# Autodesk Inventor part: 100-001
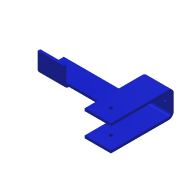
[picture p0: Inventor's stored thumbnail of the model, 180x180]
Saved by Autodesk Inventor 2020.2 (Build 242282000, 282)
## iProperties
Created: 2014-01
Part Number: 100-001
Material: Ogólny
Document SubType Name: Modeling
Designer: F.Stasiak
Density: 1 g/cm^3
Appearance: Niebieska - farba ścienna - lśniąca
Manager: www.cadconsulting.pl
Company: Fabian Stasiak CAD Consulting
Author: F.Stasiak
Subject: Zbiór ćwiczeń. Autodesk Inventor 2020. Kurs podstawowy
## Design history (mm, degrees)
sketch "Szkic2"
  geometry: L1 (20, 120)-(20, 5); L2 (20, 5)-(-20, 5); L3 (-20, 5)-(-20, 120); L4 (-25, 120)-(-25, 0); L5 (-25, 0)-(25, 0); L6 (25, 0)-(25, 120); L7 (25, 120)-(20, 120); L8 (-20, 120)-(-25, 120); 2 further points
  constraints: 16 end point, 3 equal length, 3 perpendicular, 1 coincident, 1 midpoint, 1 parallel, 1 vertical, 2 other
  dimensions: "d2" = 5 distance of L6.end L1.start; "d3" = 120 distance of L5.end L6.end; "d4" = 50 distance between parallel lines of L6 L4
extrude "Wyciągnięcie proste1" new body sketch "Szkic2" stored distance "d5" = 50; taper "d6" = 0 deg
fillet "Zaokrąglenie1" dims "d7" = 5
fillet "Zaokrąglenie2" dims "d8" = 10
sketch "Szkic3"
  geometry: L1 (50, 0)-(50, -30) reference; L2 (12.5, -15)-(37.5, -15); 4 further points
  constraints: 3 coincident, 2 end point, 1 midpoint, 1 perpendicular
  dimensions: "d9" = 25 distance of L2.start L2.end
hole "Otwór1" sketch "Szkic3" at (12.5, -15), (37.5, -15) diameter "d10" = 6.5; stored, may be unused: countersink angle "d14" = 90 deg, drill point angle "d16" = 118 deg; dims "d11" = 6, "d12" = 4, "d13" = 2, "d15" = 8
sketch "Szkic4"
  geometry: L1 (0, 0)-(50, 0) reference; 3 further points
  constraints: 1 midpoint, 1 vertical alignment
  dimensions: "d17" = 25 distance from line of L1 point (25, 25)
hole "Otwór2" sketch "Szkic4" at (25, 25) diameter "d18" = 6.5; stored, may be unused: countersink angle "d22" = 90 deg, drill point angle "d24" = 118 deg; dims "d19" = 6, "d20" = 4, "d21" = 2, "d23" = 8
sketch "Szkic5"
  geometry: L1 (10, -25)-(120, -25) reference; L2 (120, -20)-(10, -20) reference; L3 (120, 25)-(10, 25) reference; L4 (10, -25)-(10, -20); L5 (50, -25)-(50, -20); 1 further point
  constraints: 4 end point, 2 perpendicular, 2 point on line
  dimensions: "d25" = 40 distance between parallel lines of L5 L4
extrude "Wyciągnięcie proste2" join sketch "Szkic5" distance "d26" = 150; taper "d27" = 0 deg
sketch "Szkic6"
  geometry: L1 (0, 5)-(-150, 5) reference; L2 (-150, 0)-(-150, 5) reference; L3 (0, 0)-(-150, 0) reference; L4 (-100, 0)-(-100, 5); 1 further point
  constraints: 2 end point, 2 point on line, 1 perpendicular
  dimensions: "d28" = 50 distance between parallel lines of L4 L2
extrude "Wyciągnięcie proste3" join sketch "Szkic6" distance "d29" = 10; taper "d30" = 0 deg
sketch "Szkic7"
  geometry: L1 (-150, 110)-(-150, 60) reference; L2 (-100, 60)-(-150, 60) reference; L3 (-100, 70)-(-100, 60) reference; L4 (-100, 65)-(-150, 65); 1 further point
  constraints: 2 end point, 1 midpoint, 1 perpendicular, 1 point on line
extrude "Wyciągnięcie proste4" join sketch "Szkic7" distance "d31" = 35; taper "d32" = 0 deg
fillet "Zaokrąglenie3" dims "d33" = 5
fillet "Zaokrąglenie4" dims "d34" = 10
node "Bryła1"
